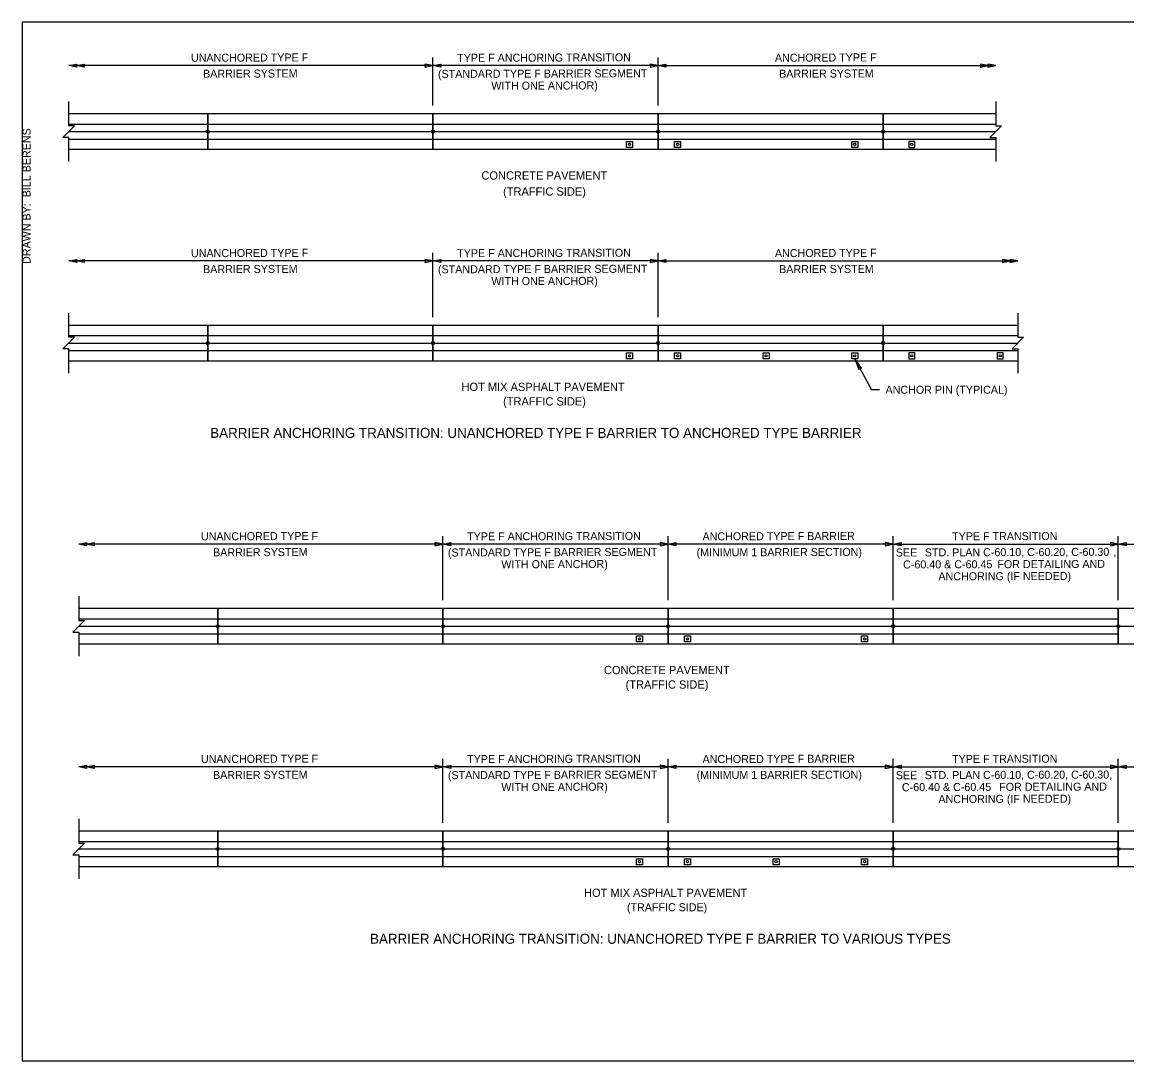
# Model space of a CAD drawing. Extents: x 99862 to 103680, y 99470 to 102076.
# Drawn here: x 99862 to 102070, y 100000 to 102076 of the extents above; entities that cross this region are included whole.
import ezdxf

# ---------------------------------------------------------------- set-up
doc = ezdxf.new("R2010")
doc.units = 0
for name, color, linetype in [('Level 1', 7, 'Continuous'), ('Level 15', 7, 'Continuous'), ('Level 2', 7, 'Continuous'), ('Level 20', 7, 'Continuous'), ('Level 60', 7, 'Continuous'), ('Level 62', 7, 'Continuous')]:
    doc.layers.add(name, color=color, linetype=linetype)

msp = doc.modelspace()

# ---------------------------------------------------------------- linework, layer by layer
at = {"layer": 'Level 1'}
msp.add_lwpolyline([(99862, 99999.5), (103151, 99999.5), (103151, 102075.5), (99862, 102075.5)], close=True, dxfattribs=at)
at = {"layer": 'Level 15'}
for p, q in [((100683, 101908.6), (100683, 102004.6)), ((101133, 101908.6), (101133, 102004.6)), ((100683, 101988.6), (99955.3, 101988.6)), ((101133, 101988.6), (100683, 101988.6)), ((101133, 101988.6), (101808, 101988.6)), ((100683, 101486.1), (100683, 101614.1)), ((101133, 101486.1), (101133, 101614.1)), ((100683, 101598.1), (99955.3, 101598.1)), ((101133, 101598.1), (100683, 101598.1)), ((101133, 101598.1), (101852.1, 101598.1)), ((101526, 101402.6), (101559.7, 101340.8)), ((101575.7, 101340.8), (101559.7, 101340.8)), ((100702.9, 100920.2), (100702.9, 101048.2)), ((101152.9, 100920.2), (101152.9, 101048.2)), ((101602.9, 100920.2), (101602.9, 101048.2)), ((102052.9, 100920.2), (102052.9, 101048.2)), ((100702.9, 101032.2), (99975.2, 101032.2)), ((101152.9, 101032.2), (100702.9, 101032.2)), ((101602.9, 101032.2), (101152.9, 101032.2)), ((101602.9, 101032.2), (102052.9, 101032.2)), ((102052.9, 101032.2), (102464.9, 101032.2)), ((100702.9, 100475.1), (100702.9, 100603.1)), ((101152.9, 100475.1), (101152.9, 100603.1)), ((101602.9, 100475.1), (101602.9, 100603.1)), ((102052.9, 100475.1), (102052.9, 100603.1)), ((100702.9, 100587.1), (99975.2, 100587.1)), ((101152.9, 100587.1), (100702.9, 100587.1)), ((101602.9, 100587.1), (101152.9, 100587.1)), ((101602.9, 100587.1), (102052.9, 100587.1)), ((102052.9, 100587.1), (102464.9, 100587.1))]:
    msp.add_line(p, q, dxfattribs=at)
for points in [[(99955.3, 101988.6), (99971.1, 101991.7), (99970.3, 101988.6), (99971.1, 101985.5)], [(99970.3, 101988.6), (99986.1, 101991.7), (99985.3, 101988.6), (99986.1, 101985.5)], [(100683, 101988.6), (100667.2, 101991.7), (100668, 101988.6), (100667.2, 101985.5)], [(100683, 101988.6), (100698.7, 101991.7), (100698, 101988.6), (100698.7, 101985.5)], [(101133, 101988.6), (101117.2, 101991.7), (101118, 101988.6), (101117.2, 101985.5)], [(101133, 101988.6), (101148.7, 101991.7), (101148, 101988.6), (101148.7, 101985.5)], [(101793, 101988.6), (101777.2, 101991.7), (101778, 101988.6), (101777.2, 101985.5)], [(101808, 101988.6), (101792.2, 101991.7), (101793, 101988.6), (101792.2, 101985.5)], [(99955.3, 101598.1), (99971.1, 101601.2), (99970.3, 101598.1), (99971.1, 101595)], [(99970.3, 101598.1), (99986.1, 101601.2), (99985.3, 101598.1), (99986.1, 101595)], [(100683, 101598.1), (100667.2, 101601.2), (100668, 101598.1), (100667.2, 101595)], [(100683, 101598.1), (100698.7, 101601.2), (100698, 101598.1), (100698.7, 101595)], [(101133, 101598.1), (101117.2, 101601.2), (101118, 101598.1), (101117.2, 101595)], [(101133, 101598.1), (101148.7, 101601.2), (101148, 101598.1), (101148.7, 101595)], [(101837.1, 101598.1), (101821.4, 101601.2), (101822.1, 101598.1), (101821.4, 101595)], [(101852.1, 101598.1), (101836.4, 101601.2), (101837.1, 101598.1), (101836.4, 101595)], [(101526, 101402.6), (101534.3, 101381.2), (101536.4, 101383.5), (101539.5, 101384)], [(99975.2, 101032.2), (99991, 101035.3), (99990.2, 101032.2), (99991, 101029.1)], [(99990.2, 101032.2), (100006, 101035.3), (100005.2, 101032.2), (100006, 101029.1)], [(100702.9, 101032.2), (100687.1, 101035.3), (100687.9, 101032.2), (100687.1, 101029.1)], [(100702.9, 101032.2), (100718.6, 101035.3), (100717.9, 101032.2), (100718.6, 101029.1)], [(101152.9, 101032.2), (101137.1, 101035.3), (101137.9, 101032.2), (101137.1, 101029.1)], [(101152.9, 101032.2), (101168.6, 101035.3), (101167.9, 101032.2), (101168.6, 101029.1)], [(101602.9, 101032.2), (101587.1, 101035.3), (101587.9, 101032.2), (101587.1, 101029.1)], [(101602.9, 101032.2), (101618.6, 101035.3), (101617.9, 101032.2), (101618.6, 101029.1)], [(102052.9, 101032.2), (102037.1, 101035.3), (102037.9, 101032.2), (102037.1, 101029.1)], [(102052.9, 101032.2), (102068.6, 101035.3), (102067.9, 101032.2), (102068.6, 101029.1)], [(99975.2, 100587.1), (99991, 100590.2), (99990.2, 100587.1), (99991, 100584.1)], [(99990.2, 100587.1), (100006, 100590.2), (100005.2, 100587.1), (100006, 100584.1)], [(100702.9, 100587.1), (100687.1, 100590.2), (100687.9, 100587.1), (100687.1, 100584.1)], [(100702.9, 100587.1), (100718.6, 100590.2), (100717.9, 100587.1), (100718.6, 100584.1)], [(101152.9, 100587.1), (101137.1, 100590.2), (101137.9, 100587.1), (101137.1, 100584.1)], [(101152.9, 100587.1), (101168.6, 100590.2), (101167.9, 100587.1), (101168.6, 100584.1)], [(101602.9, 100587.1), (101587.1, 100590.2), (101587.9, 100587.1), (101587.1, 100584.1)], [(101602.9, 100587.1), (101618.6, 100590.2), (101617.9, 100587.1), (101618.6, 100584.1)], [(102052.9, 100587.1), (102037.1, 100590.2), (102037.9, 100587.1), (102037.1, 100584.1)], [(102052.9, 100587.1), (102068.6, 100590.2), (102067.9, 100587.1), (102068.6, 100584.1)]]:
    msp.add_lwpolyline(points, close=True, dxfattribs=at)
for points in [[(99955.3, 101796.6), (99955.3, 101845), (99943.7, 101845), (99967, 101868.2), (99955.3, 101868.2), (99955.3, 101916.6)], [(101808, 101916.6), (101808, 101868.2), (101819.6, 101868.2), (101796.3, 101845), (101808, 101845), (101808, 101796.6)], [(99955.3, 101374.1), (99955.3, 101422.5), (99943.7, 101422.5), (99967, 101445.7), (99955.3, 101445.7), (99955.3, 101494.1)], [(101852.1, 101494.1), (101852.1, 101445.7), (101863.7, 101445.7), (101840.5, 101422.5), (101852.1, 101422.5), (101852.1, 101374.1)], [(99975.2, 100928.2), (99975.2, 100879.8), (99986.9, 100879.8), (99963.6, 100856.6), (99975.2, 100856.6), (99975.2, 100808.2)], [(99975.2, 100483.1), (99975.2, 100434.8), (99986.9, 100434.8), (99963.6, 100411.5), (99975.2, 100411.5), (99975.2, 100363.1)]]:
    msp.add_lwpolyline(points, dxfattribs=at)
at = {"layer": 'Level 2'}
for p, q in [((99955.3, 101892.6), (100233, 101892.6)), ((100233, 101820.6), (100233, 101892.6)), ((100233, 101892.6), (100683, 101892.6)), ((100233, 101892.6), (100233, 101820.6)), ((100683, 101820.6), (100683, 101892.6)), ((100683, 101892.6), (101133, 101892.6)), ((100683, 101892.6), (100683, 101820.6)), ((101133, 101892.6), (101133, 101820.6)), ((101133, 101820.6), (101133, 101892.6)), ((101133, 101892.6), (101583, 101892.6)), ((101583, 101892.6), (101583, 101820.6)), ((101583, 101820.6), (101583, 101892.6)), ((101583, 101892.6), (101808, 101892.6)), ((99955.3, 101871.6), (100233, 101871.6)), ((100233, 101871.6), (100683, 101871.6)), ((100683, 101871.6), (101133, 101871.6)), ((101133, 101871.6), (101583, 101871.6)), ((101583, 101871.6), (101808, 101871.6)), ((99955.3, 101856.6), (100233, 101856.6)), ((99955.3, 101841.6), (100233, 101841.6)), ((100233, 101856.6), (100683, 101856.6)), ((100233, 101841.6), (100683, 101841.6)), ((100683, 101856.6), (101133, 101856.6)), ((100683, 101841.6), (101133, 101841.6)), ((101070, 101825.1), (101070, 101837.1)), ((101070, 101837.1), (101082, 101837.1)), ((101082, 101837.1), (101082, 101825.1)), ((101133, 101856.6), (101583, 101856.6)), ((101133, 101841.6), (101583, 101841.6)), ((101166, 101825.1), (101166, 101837.1)), ((101166, 101837.1), (101178, 101837.1)), ((101178, 101837.1), (101178, 101825.1)), ((101520, 101825.1), (101520, 101837.1)), ((101520, 101837.1), (101532, 101837.1)), ((101532, 101837.1), (101532, 101825.1)), ((101583, 101856.6), (101808, 101856.6)), ((101583, 101841.6), (101808, 101841.6)), ((101646, 101837.1), (101634, 101837.1)), ((101634, 101837.1), (101634, 101825.1)), ((101646, 101825.1), (101646, 101837.1)), ((100233, 101820.6), (99955.3, 101820.6)), ((100683, 101820.6), (100233, 101820.6)), ((101133, 101820.6), (100683, 101820.6)), ((101082, 101825.1), (101070, 101825.1)), ((101583, 101820.6), (101133, 101820.6)), ((101178, 101825.1), (101166, 101825.1)), ((101532, 101825.1), (101520, 101825.1)), ((101808, 101820.6), (101583, 101820.6)), ((101634, 101825.1), (101646, 101825.1)), ((99955.3, 101470.1), (100233, 101470.1)), ((100233, 101398.1), (100233, 101470.1)), ((100233, 101470.1), (100683, 101470.1)), ((100233, 101470.1), (100233, 101398.1)), ((100683, 101470.1), (100683, 101398.1)), ((100683, 101398.1), (100683, 101470.1)), ((100683, 101470.1), (101133, 101470.1)), ((101133, 101470.1), (101133, 101398.1)), ((101133, 101398.1), (101133, 101470.1)), ((101133, 101470.1), (101583, 101470.1)), ((101583, 101470.1), (101583, 101398.1)), ((101583, 101398.1), (101583, 101470.1)), ((101583, 101470.1), (101852.1, 101470.1)), ((99955.3, 101449.1), (100233, 101449.1)), ((100233, 101449.1), (100683, 101449.1)), ((100683, 101449.1), (101133, 101449.1)), ((101133, 101449.1), (101583, 101449.1)), ((101583, 101449.1), (101852.1, 101449.1)), ((99955.3, 101434.1), (100233, 101434.1)), ((99955.3, 101419.1), (100233, 101419.1)), ((100233, 101434.1), (100683, 101434.1)), ((100233, 101419.1), (100683, 101419.1)), ((100683, 101434.1), (101133, 101434.1)), ((100683, 101419.1), (101133, 101419.1)), ((101133, 101434.1), (101583, 101434.1)), ((101133, 101419.1), (101583, 101419.1)), ((101583, 101434.1), (101852.1, 101434.1)), ((101583, 101419.1), (101852.1, 101419.1)), ((100233, 101398.1), (99955.3, 101398.1)), ((100683, 101398.1), (100233, 101398.1)), ((101133, 101398.1), (100683, 101398.1)), ((101070, 101402.6), (101070, 101414.6)), ((101070, 101414.6), (101082, 101414.6)), ((101082, 101402.6), (101070, 101402.6)), ((101082, 101414.6), (101082, 101402.6)), ((101583, 101398.1), (101133, 101398.1)), ((101166, 101402.6), (101166, 101414.6)), ((101166, 101414.6), (101178, 101414.6)), ((101178, 101402.6), (101166, 101402.6)), ((101178, 101414.6), (101178, 101402.6)), ((101343, 101402.6), (101343, 101414.6)), ((101343, 101414.6), (101355, 101414.6)), ((101355, 101402.6), (101343, 101402.6)), ((101355, 101414.6), (101355, 101402.6)), ((101520, 101402.6), (101520, 101414.6)), ((101520, 101414.6), (101532, 101414.6)), ((101532, 101402.6), (101520, 101402.6)), ((101532, 101414.6), (101532, 101402.6)), ((101852.1, 101398.1), (101583, 101398.1)), ((101646, 101414.6), (101634, 101414.6)), ((101634, 101414.6), (101634, 101402.6)), ((101634, 101402.6), (101646, 101402.6)), ((101646, 101402.6), (101646, 101414.6)), ((101823, 101414.6), (101811, 101414.6)), ((101811, 101414.6), (101811, 101402.6)), ((101811, 101402.6), (101823, 101402.6)), ((101823, 101402.6), (101823, 101414.6)), ((99975.2, 100904.2), (100252.9, 100904.2)), ((100252.9, 100904.2), (100252.9, 100832.2)), ((100252.9, 100832.2), (100252.9, 100904.2)), ((100252.9, 100904.2), (100702.9, 100904.2)), ((100702.9, 100832.2), (100702.9, 100904.2)), ((100702.9, 100904.2), (101152.9, 100904.2)), ((100702.9, 100832.2), (100702.9, 100904.2)), ((100702.9, 100904.2), (100702.9, 100832.2)), ((101152.9, 100832.2), (101152.9, 100904.2)), ((101152.9, 100904.2), (101602.9, 100904.2)), ((101152.9, 100904.2), (101152.9, 100832.2)), ((101602.9, 100904.2), (101602.9, 100832.2)), ((101602.9, 100832.2), (101602.9, 100904.2)), ((101602.9, 100904.2), (102052.9, 100904.2)), ((102052.9, 100904.2), (102052.9, 100832.2)), ((102052.9, 100832.2), (102052.9, 100904.2)), ((102052.9, 100904.2), (102464.9, 100904.2)), ((99975.2, 100883.2), (100252.9, 100883.2)), ((99975.2, 100868.2), (100252.9, 100868.2)), ((100252.9, 100883.2), (100702.9, 100883.2)), ((100252.9, 100868.2), (100702.9, 100868.2)), ((100702.9, 100883.2), (101152.9, 100883.2)), ((100702.9, 100868.2), (101152.9, 100868.2)), ((101152.9, 100883.2), (101602.9, 100883.2)), ((101152.9, 100868.2), (101602.9, 100868.2)), ((101602.9, 100883.2), (102052.9, 100883.2)), ((101602.9, 100868.2), (102052.9, 100868.2)), ((102052.9, 100868.2), (102464.9, 100868.2)), ((99975.2, 100853.2), (100252.9, 100853.2)), ((100252.9, 100853.2), (100702.9, 100853.2)), ((100702.9, 100853.2), (101152.9, 100853.2)), ((101089.9, 100836.7), (101089.9, 100848.7)), ((101089.9, 100848.7), (101101.9, 100848.7)), ((101101.9, 100848.7), (101101.9, 100836.7)), ((101152.9, 100853.2), (101602.9, 100853.2)), ((101185.9, 100836.7), (101185.9, 100848.7)), ((101185.9, 100848.7), (101197.9, 100848.7)), ((101197.9, 100848.7), (101197.9, 100836.7)), ((101539.9, 100836.7), (101539.9, 100848.7)), ((101539.9, 100848.7), (101551.9, 100848.7)), ((101551.9, 100848.7), (101551.9, 100836.7)), ((101602.9, 100853.2), (102052.9, 100853.2)), ((100252.9, 100832.2), (99975.2, 100832.2)), ((100702.9, 100832.2), (100252.9, 100832.2)), ((101152.9, 100832.2), (100702.9, 100832.2)), ((101101.9, 100836.7), (101089.9, 100836.7)), ((101602.9, 100832.2), (101152.9, 100832.2)), ((101197.9, 100836.7), (101185.9, 100836.7)), ((101551.9, 100836.7), (101539.9, 100836.7)), ((102052.9, 100832.2), (101602.9, 100832.2)), ((102464.9, 100832.2), (102052.9, 100832.2)), ((99975.2, 100459.1), (100252.9, 100459.1)), ((100252.9, 100459.1), (100252.9, 100387.1)), ((100252.9, 100387.1), (100252.9, 100459.1)), ((100252.9, 100459.1), (100702.9, 100459.1)), ((100702.9, 100387.1), (100702.9, 100459.1)), ((100702.9, 100459.1), (101152.9, 100459.1)), ((100702.9, 100387.1), (100702.9, 100459.1)), ((100702.9, 100459.1), (100702.9, 100387.1)), ((101152.9, 100387.1), (101152.9, 100459.1)), ((101152.9, 100459.1), (101602.9, 100459.1)), ((101152.9, 100459.1), (101152.9, 100387.1)), ((101602.9, 100459.1), (101602.9, 100387.1)), ((101602.9, 100387.1), (101602.9, 100459.1)), ((101602.9, 100459.1), (102052.9, 100459.1)), ((102052.9, 100459.1), (102052.9, 100387.1)), ((102052.9, 100387.1), (102052.9, 100459.1)), ((102052.9, 100459.1), (102464.9, 100459.1)), ((99975.2, 100438.1), (100252.9, 100438.1)), ((99975.2, 100423.1), (100252.9, 100423.1)), ((100252.9, 100438.1), (100702.9, 100438.1)), ((100252.9, 100423.1), (100702.9, 100423.1)), ((100702.9, 100438.1), (101152.9, 100438.1)), ((100702.9, 100423.1), (101152.9, 100423.1)), ((101152.9, 100438.1), (101602.9, 100438.1)), ((101152.9, 100423.1), (101602.9, 100423.1)), ((101602.9, 100438.1), (102052.9, 100438.1)), ((101602.9, 100423.1), (102052.9, 100423.1)), ((102052.9, 100423.1), (102464.9, 100423.1)), ((99975.2, 100408.1), (100252.9, 100408.1)), ((100252.9, 100408.1), (100702.9, 100408.1)), ((100702.9, 100408.1), (101152.9, 100408.1)), ((101089.9, 100391.6), (101089.9, 100403.6)), ((101089.9, 100403.6), (101101.9, 100403.6)), ((101101.9, 100403.6), (101101.9, 100391.6)), ((101152.9, 100408.1), (101602.9, 100408.1)), ((101185.9, 100391.6), (101185.9, 100403.6)), ((101185.9, 100403.6), (101197.9, 100403.6)), ((101197.9, 100403.6), (101197.9, 100391.6)), ((101362.9, 100391.6), (101362.9, 100403.6)), ((101362.9, 100403.6), (101374.9, 100403.6)), ((101374.9, 100403.6), (101374.9, 100391.6)), ((101539.9, 100391.6), (101539.9, 100403.6)), ((101539.9, 100403.6), (101551.9, 100403.6)), ((101551.9, 100403.6), (101551.9, 100391.6)), ((101602.9, 100408.1), (102052.9, 100408.1)), ((100252.9, 100387.1), (99975.2, 100387.1)), ((100702.9, 100387.1), (100252.9, 100387.1)), ((101152.9, 100387.1), (100702.9, 100387.1)), ((101101.9, 100391.6), (101089.9, 100391.6)), ((101602.9, 100387.1), (101152.9, 100387.1)), ((101197.9, 100391.6), (101185.9, 100391.6)), ((101374.9, 100391.6), (101362.9, 100391.6)), ((101551.9, 100391.6), (101539.9, 100391.6)), ((102052.9, 100387.1), (101602.9, 100387.1)), ((102464.9, 100387.1), (102052.9, 100387.1))]:
    msp.add_line(p, q, dxfattribs=at)
for centre, radius in [((100233, 101856.6), 3), ((100233, 101856.6), 3), ((100683, 101856.6), 3), ((100683, 101856.6), 3), ((101133, 101856.6), 3), ((101133, 101856.6), 3), ((101133, 101856.6), 3), ((101583, 101856.6), 3), ((101583, 101856.6), 3), ((101076, 101831.1), 2.25), ((101172, 101831.1), 2.25), ((101526, 101831.1), 2.25), ((101640, 101831.1), 2.25), ((100233, 101434.1), 3), ((100233, 101434.1), 3), ((100683, 101434.1), 3), ((100683, 101434.1), 3), ((101133, 101434.1), 3), ((101583, 101434.1), 3), ((101076, 101408.6), 2.25), ((101172, 101408.6), 2.25), ((101349, 101408.6), 2.25), ((101526, 101408.6), 2.25), ((101640, 101408.6), 2.25), ((101817, 101408.6), 2.25), ((100252.9, 100868.2), 3), ((100252.9, 100868.2), 3), ((100702.9, 100868.2), 3), ((100702.9, 100868.2), 3), ((100702.9, 100868.2), 3), ((100702.9, 100868.2), 3), ((101152.9, 100868.2), 3), ((101152.9, 100868.2), 3), ((101602.9, 100868.2), 3), ((101602.9, 100868.2), 3), ((101602.9, 100868.2), 3), ((102052.9, 100868.2), 3), ((101095.9, 100842.7), 2.25), ((101191.9, 100842.7), 2.25), ((101545.9, 100842.7), 2.25), ((100252.9, 100423.1), 3), ((100252.9, 100423.1), 3), ((100702.9, 100423.1), 3), ((100702.9, 100423.1), 3), ((100702.9, 100423.1), 3), ((100702.9, 100423.1), 3), ((101152.9, 100423.1), 3), ((101152.9, 100423.1), 3), ((101602.9, 100423.1), 3), ((101602.9, 100423.1), 3), ((101602.9, 100423.1), 3), ((102052.9, 100423.1), 3), ((101095.9, 100397.6), 2.25), ((101191.9, 100397.6), 2.25), ((101368.9, 100397.6), 2.25), ((101545.9, 100397.6), 2.25)]:
    msp.add_circle(centre, radius, dxfattribs=at)
at = {"layer": 'Level 60'}
msp.add_line((99862, 99999.5), (99862, 99999.5), dxfattribs=at)

# ---------------------------------------------------------------- texts
at = {"layer": 'Level 2'}
for height, p in [(16.5, (100823.3, 101728.8)), (16.5, (100823.3, 101309.3)), (16.5, (101068.2, 100743.4)), (16, (101070.8, 100298.6))]:
    msp.add_text('(TRAFFIC SIDE)', height=height, dxfattribs=at).set_placement(p)
at = {"layer": 'Level 20'}
for s, rotation, p in [('UNANCHORED TYPE F', 0.1816, (100199.6, 101996.2)), ('TYPE F ANCHORING TRANSITION', 0.1816, (100731.6, 101996)), ('ANCHORED TYPE F', 0.1816, (101366.6, 101996.3)), ('BARRIER SYSTEM', 0.1816, (100223.7, 101964.3)), ('(STANDARD TYPE F BARRIER SEGMENT', 0.1816, (100693.2, 101963.9)), ('BARRIER SYSTEM', 0.1816, (101375, 101964.3)), ('WITH ONE ANCHOR)', 0.1816, (100799.9, 101940.3)), ('UNANCHORED TYPE F', 0.1816, (100199.6, 101605.7)), ('TYPE F ANCHORING TRANSITION', 0.1816, (100731.6, 101605.6)), ('ANCHORED TYPE F', 0.1816, (101366.6, 101605.8)), ('BARRIER SYSTEM', 0.1816, (100223.7, 101573.8)), ('(STANDARD TYPE F BARRIER SEGMENT', 0.1816, (100693.2, 101573.4)), ('BARRIER SYSTEM', 0.1816, (101375, 101573.8)), ('WITH ONE ANCHOR)', 0.1816, (100799.9, 101549.8)), ('ANCHOR PIN (TYPICAL)', 360, (101587.7, 101332.8)), ('UNANCHORED TYPE F', 0.1816, (100219.5, 101039.8)), ('TYPE F ANCHORING TRANSITION', 0.1816, (100751.5, 101039.6)), ('ANCHORED TYPE F BARRIER', 0.1816, (101221.9, 101039.7)), ('TYPE F TRANSITION', 0.1816, (101720.7, 101039.9)), ('BARRIER SYSTEM', 0.1816, (100243.6, 101007.9)), ('(STANDARD TYPE F BARRIER SEGMENT', 0.1816, (100713.1, 101007.5)), ('(MINIMUM 1 BARRIER SECTION)', 0.1816, (101210, 101007.7)), ('SEE ', 0.1816, (101608.2, 101007.5)), ('STD. PLAN C-60.10, C-60.20, C-60.30', 0.1816, (101666.2, 101007.7)), ('WITH ONE ANCHOR)', 0.1816, (100819.8, 100983.9)), ('C-60.40 & C-60.45', 0.1816, (101622.8, 100983.6)), (' FOR DETAILING AND', 0.1816, (101805.2, 100984.1)), (',', 0.1816, (102043, 101008.9)), ('ANCHORING (IF NEEDED)', 0.1816, (101693.4, 100959.8)), ('UNANCHORED TYPE F', 0.1816, (100219.5, 100594.8)), ('TYPE F ANCHORING TRANSITION', 0.1816, (100751.5, 100594.6)), ('ANCHORED TYPE F BARRIER', 0.1816, (101221.9, 100594.6)), ('TYPE F TRANSITION', 0.1816, (101720.7, 100594.8)), ('BARRIER SYSTEM', 0.1816, (100243.6, 100562.8)), ('(STANDARD TYPE F BARRIER SEGMENT', 0.1816, (100713.1, 100562.5)), ('(MINIMUM 1 BARRIER SECTION)', 0.1816, (101210, 100562.6)), ('SEE ', 0.1816, (101608.1, 100562.4)), ('STD. PLAN C-60.10, C-60.20, C-60.30,', 0.1816, (101666, 100562.6)), ('WITH ONE ANCHOR)', 0.1816, (100819.8, 100538.8)), ('C-60.40 & C-60.45 ', 0.1816, (101620.4, 100538.5)), ('FOR DETAILING AND', 0.1816, (101814.9, 100539.1)), ('ANCHORING (IF NEEDED)', 0.1816, (101693.4, 100514.7))]:
    msp.add_text(s, height=16, rotation=rotation, dxfattribs=at).set_placement(p)
for s, height, p in [('CONCRETE PAVEMENT', 16.5, (100780, 101760.8)), ('HOT MIX ASPHALT PAVEMENT', 16.5, (100740.2, 101338.3)), ('BARRIER ANCHORING TRANSITION: UNANCHORED TYPE F BARRIER TO ANCHORED TYPE BARRIER', 20, (100238, 101244.6)), ('CONCRETE PAVEMENT', 16.5, (101024.9, 100772.4)), ('HOT MIX ASPHALT PAVEMENT', 16.5, (100985.1, 100327.3)), ('BARRIER ANCHORING TRANSITION: UNANCHORED TYPE F BARRIER TO VARIOUS TYPES', 20, (100557.4, 100233.6))]:
    msp.add_text(s, height=height, dxfattribs=at).set_placement(p)
at = {"layer": 'Level 62'}
msp.add_text('DRAWN BY:  BILL BERENS', height=16, rotation=90, dxfattribs=at).set_placement((99879, 101592.2))

doc.saveas('drawing.dxf')
